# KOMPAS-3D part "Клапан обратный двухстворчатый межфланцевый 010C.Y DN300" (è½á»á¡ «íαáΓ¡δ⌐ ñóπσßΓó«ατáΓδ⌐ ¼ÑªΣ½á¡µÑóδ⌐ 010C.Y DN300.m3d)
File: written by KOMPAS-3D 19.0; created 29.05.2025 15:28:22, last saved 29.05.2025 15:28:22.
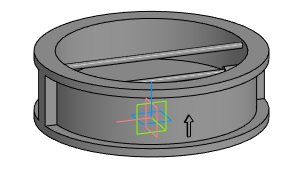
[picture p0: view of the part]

Document properties: Полное имя файла: E:\Dendor Работа Сачек\3D для проекитирвщиков\5.2 Тип 010C, 010C.Y Клапан обратный двухстворчатый межфланцевый\stp_Клапан обратный двухстворчатый межфланцевый 010C.Y\Клапан обратный двухстворчатый межфланцевый 010C.Y DN300.m3d

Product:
- Part/product: Клапан обратный двухстворчатый межфланцевый 010C.Y DN300

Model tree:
1. Операция без истории:1  (labels: Клапан обратный двухстворчатый межфланцевый 010C.Y DN300)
